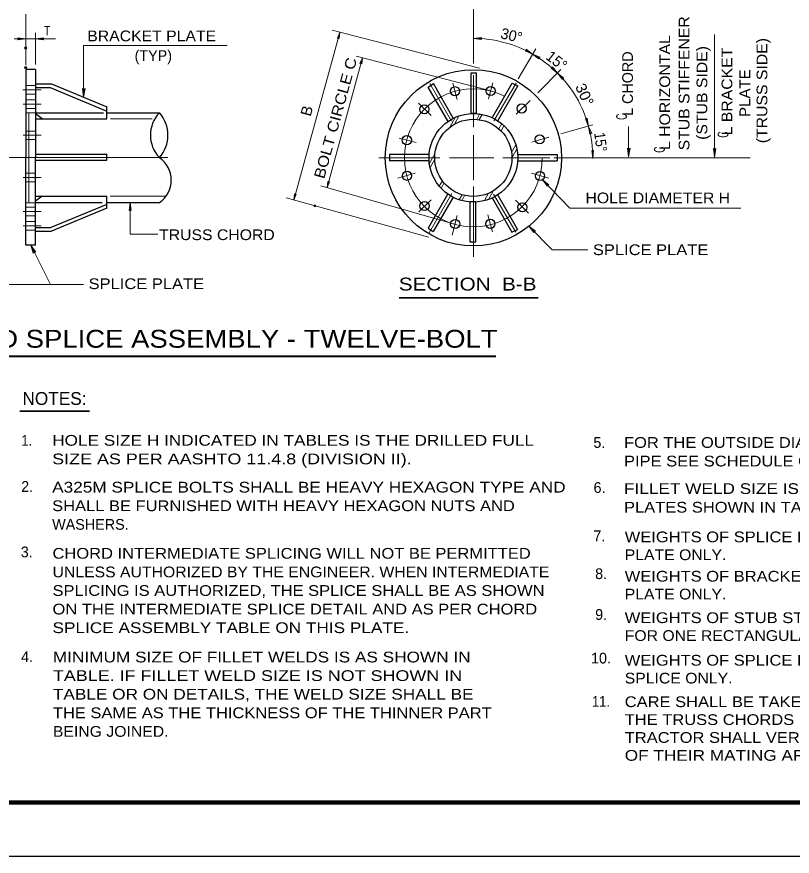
# Model space of a CAD drawing. Extents: x 312601.858 to 312602.699, y 144420.109 to 144420.704.
# Drawn here: x 312602.0139 to 312602.2309, y 144420.1095 to 144420.3443 of the extents above; entities that cross this region are included whole.
import ezdxf
from ezdxf.enums import TextEntityAlignment as Align

# ---------------------------------------------------------------- set-up
doc = ezdxf.new("R2010")
doc.units = 0
doc.header["$LTSCALE"] = 0.0012
doc.header["$PDMODE"] = 32
doc.header["$PDSIZE"] = 0.0006
doc.linetypes.add('DOT_DASHED', pattern=[7.7, 5, -1.2, 0.3, -1.2])
doc.linetypes.add('LONG_DASHED', pattern=[7.5, 6, -1.5])
for name, color, linetype, lineweight in [('1', 7, 'Continuous', 13), ('2', 7, 'Continuous', 25), ('39', 7, 'Continuous', 13)]:
    doc.layers.add(name, color=color, linetype=linetype, lineweight=lineweight)

msp = doc.modelspace()

# ---------------------------------------------------------------- hatches: boundary and pattern name
at = {"layer": '39'}
for points in [[(312602.1039, 144420.3384), (312602.1036, 144420.3383), (312602.1043, 144420.3399), (312602.1041, 144420.3382)], [(312602.1102, 144420.3313), (312602.1099, 144420.3312), (312602.1106, 144420.3328), (312602.1104, 144420.3311)], [(312602.0326, 144420.324), (312602.033, 144420.3242), (312602.0326, 144420.3218), (312602.0323, 144420.3242)], [(312602.1851, 144420.3073), (312602.1855, 144420.3075), (312602.1851, 144420.3051), (312602.1848, 144420.3075)], [(312602.2091, 144420.3072), (312602.2095, 144420.3074), (312602.2091, 144420.305), (312602.2088, 144420.3074)], [(312602.1011, 144420.298), (312602.1014, 144420.2981), (312602.1007, 144420.2965), (312602.1009, 144420.2982)], [(312602.0918, 144420.2945), (312602.0921, 144420.2946), (312602.0914, 144420.293), (312602.0916, 144420.2947)], [(312602.0188, 144420.2785), (312602.0185, 144420.2781), (312602.0178, 144420.2804), (312602.0192, 144420.2784)]]:
    msp.add_hatch(color=256, dxfattribs=at).paths.add_polyline_path(points)

# ---------------------------------------------------------------- linework, layer by layer
at = {"layer": '1'}
for p, q in [((312602.1417, 144420.3312), (312602.1417, 144420.3642)), ((312602.0164, 144420.3307), (312602.0164, 144420.345)), ((312602.1434, 144420.3299), (312602.1021, 144420.3405)), ((312602.0191, 144420.3398), (312602.0191, 144420.3309)), ((312602.0914, 144420.293), (312602.1043, 144420.3399)), ((312602.2091, 144420.3393), (312602.2091, 144420.3061)), ((312602.1542, 144420.3269), (312602.1591, 144420.3353)), ((312602.1007, 144420.2965), (312602.1106, 144420.3328)), ((312602.1465, 144420.3235), (312602.1089, 144420.3332)), ((312602.1597, 144420.323), (312602.1661, 144420.3295)), ((312602.0191, 144420.3174), (312602.0164, 144420.3174)), ((312602.1661, 144420.3115), (312602.1751, 144420.314)), ((312602.1851, 144420.3136), (312602.1851, 144420.3051)), ((312602.1417, 144420.2986), (312602.1417, 144420.3111)), ((312602.135, 144420.3048), (312602.1474, 144420.3048)), ((312602.1642, 144420.3048), (312602.2191, 144420.3048)), ((312602.1686, 144420.2907), (312602.161, 144420.2987)), ((312602.1364, 144420.2863), (312602.099, 144420.297)), ((312602.1292, 144420.2826), (312602.0893, 144420.2936)), ((312602.0192, 144420.2922), (312602.0165, 144420.2922)), ((312602.1686, 144420.2907), (312602.2165, 144420.2907)), ((312602.1637, 144420.2791), (312602.1572, 144420.2857)), ((312602.1636, 144420.2791), (312602.1737, 144420.2791))]:
    msp.add_line(p, q, dxfattribs=at)
at = {"layer": '1', "lineweight": 25}
for p, q in [((312602.0191, 144420.3295), (312602.0164, 144420.3295)), ((312602.0164, 144420.3295), (312602.0164, 144420.3049)), ((312602.0191, 144420.3295), (312602.0191, 144420.3049)), ((312602.129, 144420.3246), (312602.1305, 144420.3256)), ((312602.1346, 144420.315), (312602.129, 144420.3246)), ((312602.136, 144420.3159), (312602.1305, 144420.3256)), ((312602.1469, 144420.316), (312602.1525, 144420.3257)), ((312602.1485, 144420.3152), (312602.1541, 144420.3249)), ((312602.1525, 144420.3257), (312602.1541, 144420.3249)), ((312602.021, 144420.3157), (312602.0191, 144420.3171)), ((312602.0391, 144420.3174), (312602.0538, 144420.3174)), ((312602.1182, 144420.3057), (312602.1182, 144420.304)), ((312602.1292, 144420.3057), (312602.1182, 144420.3057)), ((312602.1541, 144420.3057), (312602.1651, 144420.3057)), ((312602.1651, 144420.3057), (312602.1651, 144420.304)), ((312602.0164, 144420.2804), (312602.0164, 144420.3049)), ((312602.0191, 144420.2804), (312602.0191, 144420.3049)), ((312602.1292, 144420.304), (312602.1182, 144420.304)), ((312602.1541, 144420.304), (312602.1651, 144420.304)), ((312602.021, 144420.2941), (312602.0191, 144420.2927)), ((312602.1345, 144420.2947), (312602.129, 144420.2851)), ((312602.136, 144420.2938), (312602.1304, 144420.2842)), ((312602.1469, 144420.2936), (312602.1524, 144420.284)), ((312602.1485, 144420.2944), (312602.154, 144420.2848)), ((312602.0391, 144420.2923), (312602.0538, 144420.2923)), ((312602.129, 144420.2851), (312602.1304, 144420.2842)), ((312602.1524, 144420.284), (312602.154, 144420.2848)), ((312602.0191, 144420.2804), (312602.0164, 144420.2804))]:
    msp.add_line(p, q, dxfattribs=at)
at = {"layer": '1', "linetype": 'LONG_DASHED'}
for p, q in [((312602.1417, 144420.3134), (312602.1417, 144420.3279)), ((312602.019, 144420.325), (312602.0163, 144420.325)), ((312602.019, 144420.3226), (312602.0163, 144420.3226)), ((312602.0191, 144420.321), (312602.0164, 144420.321)), ((312602.0191, 144420.3186), (312602.0164, 144420.3186)), ((312602.0173, 144420.3174), (312602.0173, 144420.3049)), ((312602.0191, 144420.3174), (312602.019, 144420.3174)), ((312602.0401, 144420.3157), (312602.0518, 144420.3157)), ((312602.0191, 144420.3123), (312602.0164, 144420.3123)), ((312602.0191, 144420.3099), (312602.0164, 144420.3099)), ((312602.0173, 144420.2923), (312602.0173, 144420.3049)), ((312602.1152, 144420.3048), (312602.1323, 144420.3048)), ((312602.1499, 144420.3048), (312602.163, 144420.3048)), ((312602.0191, 144420.3005), (312602.0164, 144420.3005)), ((312602.0191, 144420.2981), (312602.0164, 144420.2981)), ((312602.1417, 144420.2771), (312602.1417, 144420.2968)), ((312602.04, 144420.2941), (312602.0557, 144420.2941)), ((312602.0191, 144420.291), (312602.0164, 144420.291)), ((312602.0191, 144420.2886), (312602.0164, 144420.2886)), ((312602.0191, 144420.287), (312602.0164, 144420.287)), ((312602.0191, 144420.2846), (312602.0164, 144420.2846))]:
    msp.add_line(p, q, dxfattribs=at)
at = {"layer": '1', "linetype": 'DOT_DASHED'}
for p, q in [((312602.1355, 144420.3151), (312602.1295, 144420.3256)), ((312602.1371, 144420.3211), (312602.1359, 144420.3257)), ((312602.1459, 144420.3213), (312602.1471, 144420.3258)), ((312602.1474, 144420.3152), (312602.1536, 144420.3257)), ((312602.0156, 144420.3238), (312602.0207, 144420.3238)), ((312602.0157, 144420.3198), (312602.0207, 144420.3198)), ((312602.1298, 144420.3166), (312602.1263, 144420.3201)), ((312602.1536, 144420.317), (312602.1575, 144420.3208)), ((312602.0157, 144420.3111), (312602.0207, 144420.3111)), ((312602.1256, 144420.3091), (312602.1209, 144420.3103)), ((312602.158, 144420.3092), (312602.1628, 144420.3106)), ((312601.9562, 144420.3049), (312602.0586, 144420.3049)), ((312602.1205, 144420.2991), (312602.1254, 144420.3005)), ((312602.1628, 144420.2991), (312602.1579, 144420.3005)), ((312602.0157, 144420.2993), (312602.0207, 144420.2993)), ((312602.1293, 144420.2838), (312602.1356, 144420.2948)), ((312602.1535, 144420.284), (312602.1473, 144420.2946)), ((312602.1264, 144420.2897), (312602.1298, 144420.2931)), ((312602.1571, 144420.2893), (312602.1534, 144420.293)), ((312602.0157, 144420.2898), (312602.0207, 144420.2898)), ((312602.147, 144420.2841), (312602.1457, 144420.2889)), ((312602.1357, 144420.2832), (312602.1371, 144420.2887)), ((312602.0157, 144420.2858), (312602.0207, 144420.2858))]:
    msp.add_line(p, q, dxfattribs=at)
at = {"layer": '1', "linetype": 'LONG_DASHED', "lineweight": 25}
for p, q in [((312602.0191, 144420.3174), (312602.0382, 144420.3174)), ((312602.0191, 144420.2923), (312602.0378, 144420.2923))]:
    msp.add_line(p, q, dxfattribs=at)
at = {"layer": '1', "lineweight": 40}
msp.add_line((312601.9855, 144420.2493), (312602.1479, 144420.2493), dxfattribs=at)
at = {"layer": '1'}
for points in [[(312602.0132, 144420.3381), (312602.0164, 144420.3381), (312602.0191, 144420.3381), (312602.0247, 144420.3381)], [(312602.0326, 144420.3218), (312602.0326, 144420.3362), (312602.0728, 144420.3362)], [(312602.0456, 144420.2923), (312602.0456, 144420.2835), (312602.0534, 144420.2835)]]:
    msp.add_lwpolyline(points, dxfattribs=at)
for points in [[(312602.0142, 144420.3384), (312602.0164, 144420.3381), (312602.0142, 144420.3378), (312602.0144, 144420.3381)], [(312602.0214, 144420.3378), (312602.0191, 144420.3381), (312602.0214, 144420.3384), (312602.0211, 144420.3381)], [(312602.1439, 144420.3379), (312602.1417, 144420.3382), (312602.1439, 144420.3385), (312602.1437, 144420.3382)], [(312602.1564, 144420.3352), (312602.1582, 144420.3338), (312602.1561, 144420.3347), (312602.1565, 144420.3348)], [(312602.16, 144420.3325), (312602.1582, 144420.3338), (312602.1603, 144420.333), (312602.16, 144420.3328)], [(312602.1638, 144420.3303), (312602.1652, 144420.3285), (312602.1634, 144420.3299), (312602.1637, 144420.3299)], [(312602.1666, 144420.3267), (312602.1652, 144420.3285), (312602.167, 144420.3271), (312602.1666, 144420.3271)], [(312602.1735, 144420.3159), (312602.1739, 144420.3136), (312602.173, 144420.3157), (312602.1733, 144420.3156)], [(312602.1742, 144420.3114), (312602.1739, 144420.3136), (312602.1748, 144420.3116), (312602.1744, 144420.3117)], [(312602.1753, 144420.3069), (312602.1751, 144420.3046), (312602.1748, 144420.3069), (312602.1751, 144420.3067)], [(312602.1624, 144420.2969), (312602.161, 144420.2987), (312602.1628, 144420.2973), (312602.1624, 144420.2972)], [(312602.0453, 144420.2901), (312602.0456, 144420.2923), (312602.0459, 144420.2901), (312602.0456, 144420.2903)], [(312602.1586, 144420.2839), (312602.1572, 144420.2857), (312602.159, 144420.2843), (312602.1586, 144420.2843)]]:
    msp.add_lwpolyline(points, close=True, dxfattribs=at)
at = {"layer": '1', "lineweight": 25}
for points in [[(312602.1409, 144420.3173), (312602.1425, 144420.3173), (312602.1425, 144420.3285), (312602.1409, 144420.3285)], [(312602.1407, 144420.2813), (312602.1423, 144420.2813), (312602.1423, 144420.2925), (312602.1407, 144420.2925)]]:
    msp.add_lwpolyline(points, close=True, dxfattribs=at)
for centre, radius in [((312602.14165, 144420.30481), 0.02465), ((312602.136538, 144420.323439), 0.001275), ((312602.146495, 144420.32351), 0.001275), ((312602.127951, 144420.318398), 0.001275), ((312602.155153, 144420.318594), 0.001275), ((312602.14165, 144420.30481), 0.01241), ((312602.14165, 144420.30481), 0.010795), ((312602.123035, 144420.30974), 0.001275), ((312602.160194, 144420.310007), 0.001275), ((312602.123106, 144420.299783), 0.001275), ((312602.160265, 144420.29971), 0.001275), ((312602.127977, 144420.291366), 0.001275), ((312602.155349, 144420.290967), 0.001275), ((312602.13655, 144420.28628), 0.001275), ((312602.146422, 144420.286351), 0.001275)]:
    msp.add_circle(centre, radius, dxfattribs=at)
at = {"layer": '1', "linetype": 'DOT_DASHED'}
msp.add_circle((312602.14165, 144420.30481), 0.019295, dxfattribs=at)
at = {"layer": '1'}
for start, end in [(60.28289, 89.99981), (45.20618, 60.28289), (15.33003, 45.20618), (359.72265, 15.33003)]:
    msp.add_arc((312602.14165, 144420.30481), 0.033405, start, end, dxfattribs=at)
for p in [(312602.0164, 144420.3355), (312602.0164, 144420.33), (312602.0973, 144420.2914)]:
    msp.add_point(p, dxfattribs=at)
at = {"layer": '2'}
for p, q in [((312602.0191, 144420.3255), (312602.0236, 144420.3255)), ((312602.0191, 144420.3245), (312602.0232, 144420.3245)), ((312602.0232, 144420.3245), (312602.0391, 144420.3179)), ((312602.0236, 144420.3255), (312602.0391, 144420.3191)), ((312602.0391, 144420.3157), (312602.0391, 144420.3191)), ((312602.0191, 144420.3157), (312602.0391, 144420.3157)), ((312602.0191, 144420.3058), (312602.0391, 144420.3058)), ((312602.0391, 144420.3042), (312602.0391, 144420.3058)), ((312602.0191, 144420.3042), (312602.0391, 144420.3042)), ((312602.0191, 144420.2941), (312602.0391, 144420.2941)), ((312602.0391, 144420.2907), (312602.0391, 144420.2941)), ((312602.0391, 144420.2918), (312602.0232, 144420.2852)), ((312602.0391, 144420.2907), (312602.0236, 144420.2843)), ((312602.0191, 144420.2853), (312602.0234, 144420.2853)), ((312602.0191, 144420.2843), (312602.0236, 144420.2843))]:
    msp.add_line(p, q, dxfattribs=at)
at = {"layer": '2', "lineweight": 13}
for p, q in [((312602.1426, 144420.3155), (312602.1435, 144420.3172)), ((312602.1433, 144420.3155), (312602.1441, 144420.3169)), ((312602.1351, 144420.3134), (312602.1366, 144420.3161)), ((312602.1365, 144420.3144), (312602.1377, 144420.3166)), ((312602.1488, 144420.3129), (312602.1496, 144420.3144)), ((312602.1494, 144420.3124), (312602.1502, 144420.3138)), ((312602.1523, 144420.3063), (312602.1535, 144420.3084)), ((312602.1293, 144420.3031), (312602.1309, 144420.3059)), ((312602.1525, 144420.3049), (312602.1538, 144420.3073)), ((312602.1296, 144420.3021), (312602.1309, 144420.3044)), ((312602.1321, 144420.2969), (312602.133, 144420.2984)), ((312602.1326, 144420.2963), (312602.1335, 144420.2978)), ((312602.1376, 144420.293), (312602.1385, 144420.2945)), ((312602.1384, 144420.2928), (312602.1392, 144420.2943)), ((312602.1448, 144420.2929), (312602.1459, 144420.2949)), ((312602.1459, 144420.2932), (312602.1472, 144420.2955)), ((312602.0178, 144420.2804), (312602.0233, 144420.2694)), ((312602.0116, 144420.2694), (312602.0326, 144420.2694))]:
    msp.add_line(p, q, dxfattribs=at)
at = {"layer": '2', "lineweight": 35}
for p, q in [((312602.1209, 144420.2657), (312602.1598, 144420.2657)), ((312602.0148, 144420.234), (312602.0342, 144420.234))]:
    msp.add_line(p, q, dxfattribs=at)
at = {"layer": '2'}
for centre, radius, start, end in [((312602.060323, 144420.31115), 0.0090337, 136.22321, 223.77679), ((312602.046867, 144420.31115), 0.0093345, 317.96716, 42.03284), ((312602.049595, 144420.29855), 0.0075326, 303.9298, 56.0702)]:
    msp.add_arc(centre, radius, start, end, dxfattribs=at)
at = {"layer": '39', "lineweight": 158}
msp.add_line((312601.9088, 144420.1245), (312602.6838, 144420.1245), dxfattribs=at)
at = {"layer": '39', "lineweight": 25}
msp.add_line((312601.8578, 144420.1095), (312602.6988, 144420.1095), dxfattribs=at)
at = {"layer": '39'}
for points in [[(312602.1039, 144420.3384), (312602.1036, 144420.3383), (312602.1043, 144420.3399), (312602.1041, 144420.3382)], [(312602.1102, 144420.3313), (312602.1099, 144420.3312), (312602.1106, 144420.3328), (312602.1104, 144420.3311)], [(312602.0326, 144420.324), (312602.033, 144420.3242), (312602.0326, 144420.3218), (312602.0323, 144420.3242)], [(312602.1851, 144420.3073), (312602.1855, 144420.3075), (312602.1851, 144420.3051), (312602.1848, 144420.3075)], [(312602.2091, 144420.3072), (312602.2095, 144420.3074), (312602.2091, 144420.305), (312602.2088, 144420.3074)], [(312602.1011, 144420.298), (312602.1014, 144420.2981), (312602.1007, 144420.2965), (312602.1009, 144420.2982)], [(312602.0918, 144420.2945), (312602.0921, 144420.2946), (312602.0914, 144420.293), (312602.0916, 144420.2947)], [(312602.0188, 144420.2785), (312602.0185, 144420.2781), (312602.0178, 144420.2804), (312602.0192, 144420.2784)]]:
    msp.add_lwpolyline(points, close=True, dxfattribs=at)

# ---------------------------------------------------------------- texts
at = {"layer": '2'}
for s, height, rotation, width, p in [('STUB STIFFENER', 0.003, 90, 1.1, (312602.2021, 144420.32565)), ('L HORIZONTAL', 0.003, 90, 1.1, (312602.1967, 144420.32305)), ('(TRUSS SIDE)', 0.003, 90, 1.1, (312602.2239, 144420.3236)), ('(STUB SIDE)', 0.003, 90, 1.1, (312602.2071, 144420.32295)), ('L BRACKET', 0.003, 90, 1.1, (312602.2141, 144420.32335)), ('BOLT CIRCLE C', 0.003, 74.631, 1.15, (312602.104515, 144420.315552)), ('PLATE', 0.003, 90, 1.05, (312602.2191, 144420.3229)), ('30°', 0.002999, 295.15, 1.05, (312602.171414, 144420.321837)), ('B', 0.003, 74.631, 1.05, (312602.096472, 144420.317552)), ('C', 0.003, 90, 0.6, (312602.1846, 144420.3163)), ('15°', 0.002999, 277.5, 0.9, (312602.175802, 144420.309046)), ('C', 0.003, 90, 0.6, (312602.213, 144420.3113)), ('C', 0.003, 90, 0.6, (312602.1952, 144420.3071))]:
    msp.add_text(s, height=height, rotation=rotation, dxfattribs=dict(at, width=width)).set_placement(p, align=Align.CENTER)
for s, height, width, p in [('T', 0.00255, 0.8, (312602.0224, 144420.3391)), ('BRACKET PLATE', 0.003, 1.1, (312602.05165, 144420.3374)), ('HOLE DIAMETER H', 0.003, 1.1, (312602.19325, 144420.2921)), ('TRUSS CHORD', 0.003, 1.1, (312602.0699, 144420.2818)), ('SPLICE PLATE', 0.003, 1.15, (312602.19125, 144420.2776)), ('SPLICE PLATE', 0.003, 1.15, (312602.05015, 144420.2681)), ('SECTION  B-B', 0.0036, 1.2, (312602.14005, 144420.2677)), ('CHORD SPLICE ASSEMBLY - TWELVE-BOLT', 0.005, 1.15, (312602.06725, 144420.2517)), ('1.', 0.003, 0.9, (312602.0167, 144420.2243)), ('11.', 0.003, 0.9, (312602.17735, 144420.1513))]:
    msp.add_text(s, height=height, dxfattribs=dict(at, width=width)).set_placement(p, align=Align.CENTER)
for s, height, rotation, p in [('30°', 0.002999, 346.49, (312602.152, 144420.337587)), ('15°', 0.002999, 322.343, (312602.164034, 144420.330804)), ('L CHORD', 0.003, 90, (312602.1863, 144420.32555))]:
    msp.add_text(s, height=height, rotation=rotation, dxfattribs=at).set_placement(p, align=Align.CENTER)
for s, height, p in [('(TYP)', 0.003, (312602.0521, 144420.3319)), ('NOTES:', 0.0036, (312602.02445, 144420.2357)), ('5.', 0.003, (312602.1769, 144420.2237)), ('2.', 0.003, (312602.0168, 144420.2114)), ('6.', 0.003, (312602.17695, 144420.2111)), ('7.', 0.003, (312602.1769, 144420.1976)), ('3.', 0.003, (312602.0167, 144420.1931)), ('8.', 0.003, (312602.1774, 144420.187)), ('9.', 0.003, (312602.1774, 144420.1756)), ('4.', 0.003, (312602.0168, 144420.1638)), ('10.', 0.003, (312602.17735, 144420.1634))]:
    msp.add_text(s, height=height, dxfattribs=at).set_placement(p, align=Align.CENTER)
for s, width, p in [('HOLE SIZE H INDICATED IN TABLES IS THE DRILLED FULL', 1.2, (312602.0238, 144420.2243)), ('FOR THE OUTSIDE DIAMETER (O.D.) OF THE STEEL STUB', 1.15, (312602.1838, 144420.2237)), ('SIZE AS PER AASHTO 11.4.8 (DIVISION II).', 1.25, (312602.0238, 144420.2191)), ('PIPE SEE SCHEDULE OF STRUCTURES ON PLATE 2.11-2.', 1.15, (312602.1838, 144420.2185)), ('A325M SPLICE BOLTS SHALL BE HEAVY HEXAGON TYPE AND ', 1.2, (312602.0238, 144420.2112)), ('FILLET WELD SIZE IS TO BE THE SAME AS FOR THE BRACKET', 1.2, (312602.1838, 144420.2108)), ('SHALL BE FURNISHED WITH HEAVY HEXAGON NUTS AND ', 1.15, (312602.0238, 144420.206)), ('PLATES SHOWN IN TABLE.', 1.15, (312602.1838, 144420.2056)), ('WEIGHTS OF SPLICE PLATES SHOWN IN THE TABLE ARE FOR ONE', 1.15, (312602.184, 144420.1973)), ('CHORD INTERMEDIATE SPLICING WILL NOT BE PERMITTED', 1.15, (312602.0239, 144420.1927)), ('PLATE ONLY.', 1.1, (312602.184, 144420.1923)), ('UNLESS AUTHORIZED BY THE ENGINEER. WHEN INTERMEDIATE', 1.1, (312602.0239, 144420.1875)), ('WEIGHTS OF BRACKET PLATES SHOWN IN THE TABLE ARE FOR ONE', 1.15, (312602.184, 144420.1863)), ('SPLICING IS AUTHORIZED, THE SPLICE SHALL BE AS SHOWN', 1.15, (312602.0239, 144420.1823)), ('PLATE ONLY.', 1.1, (312602.184, 144420.1813)), ('ON THE INTERMEDIATE SPLICE DETAIL AND AS PER CHORD', 1.15, (312602.0239, 144420.1771)), ('WEIGHTS OF STUB STIFFENER PLATES SHOWN IN THE TABLE ARE', 1.15, (312602.184, 144420.1747)), ('SPLICE ASSEMBLY TABLE ON THIS PLATE.', 1.2, (312602.0239, 144420.1719)), ('FOR ONE RECTANGULAR PLATE.', 1.1, (312602.184, 144420.1697)), ('MINIMUM SIZE OF FILLET WELDS IS AS SHOWN IN', 1.2, (312602.024, 144420.1637)), ('WEIGHTS OF SPLICE BOLTS SHOWN IN THE TABLE ARE FOR ONE ', 1.15, (312602.184, 144420.1628)), ('TABLE. IF FILLET WELD SIZE IS NOT SHOWN IN', 1.25, (312602.024, 144420.1585)), ('SPLICE ONLY.', 1.1, (312602.184, 144420.1578)), ('TABLE OR ON DETAILS, THE WELD SIZE SHALL BE', 1.2, (312602.024, 144420.1533)), ('CARE SHALL BE TAKEN TO ENSURE THAT THE SPLICE PLATES AND', 1.15, (312602.184, 144420.1512)), ('THE SAME AS THE THICKNESS OF THE THINNER PART', 1.15, (312602.024, 144420.1481)), ('THE TRUSS CHORDS DO NOT WARP DURING WELDING.  THE CON-', 1.15, (312602.184, 144420.1462)), ('BEING JOINED.', 1.1, (312602.024, 144420.1429)), ('TRACTOR SHALL VERIFY THAT THE SPLICE PLATES CONTACT 100%', 1.15, (312602.184, 144420.1412)), ('OF THEIR MATING AREA PRIOR TO SHIPPING.', 1.2, (312602.184, 144420.1362))]:
    msp.add_text(s, height=0.003, dxfattribs=dict(at, width=width)).set_placement(p)
msp.add_text('WASHERS.', height=0.003, dxfattribs=at).set_placement((312602.0238, 144420.2008))

doc.saveas('drawing.dxf')
